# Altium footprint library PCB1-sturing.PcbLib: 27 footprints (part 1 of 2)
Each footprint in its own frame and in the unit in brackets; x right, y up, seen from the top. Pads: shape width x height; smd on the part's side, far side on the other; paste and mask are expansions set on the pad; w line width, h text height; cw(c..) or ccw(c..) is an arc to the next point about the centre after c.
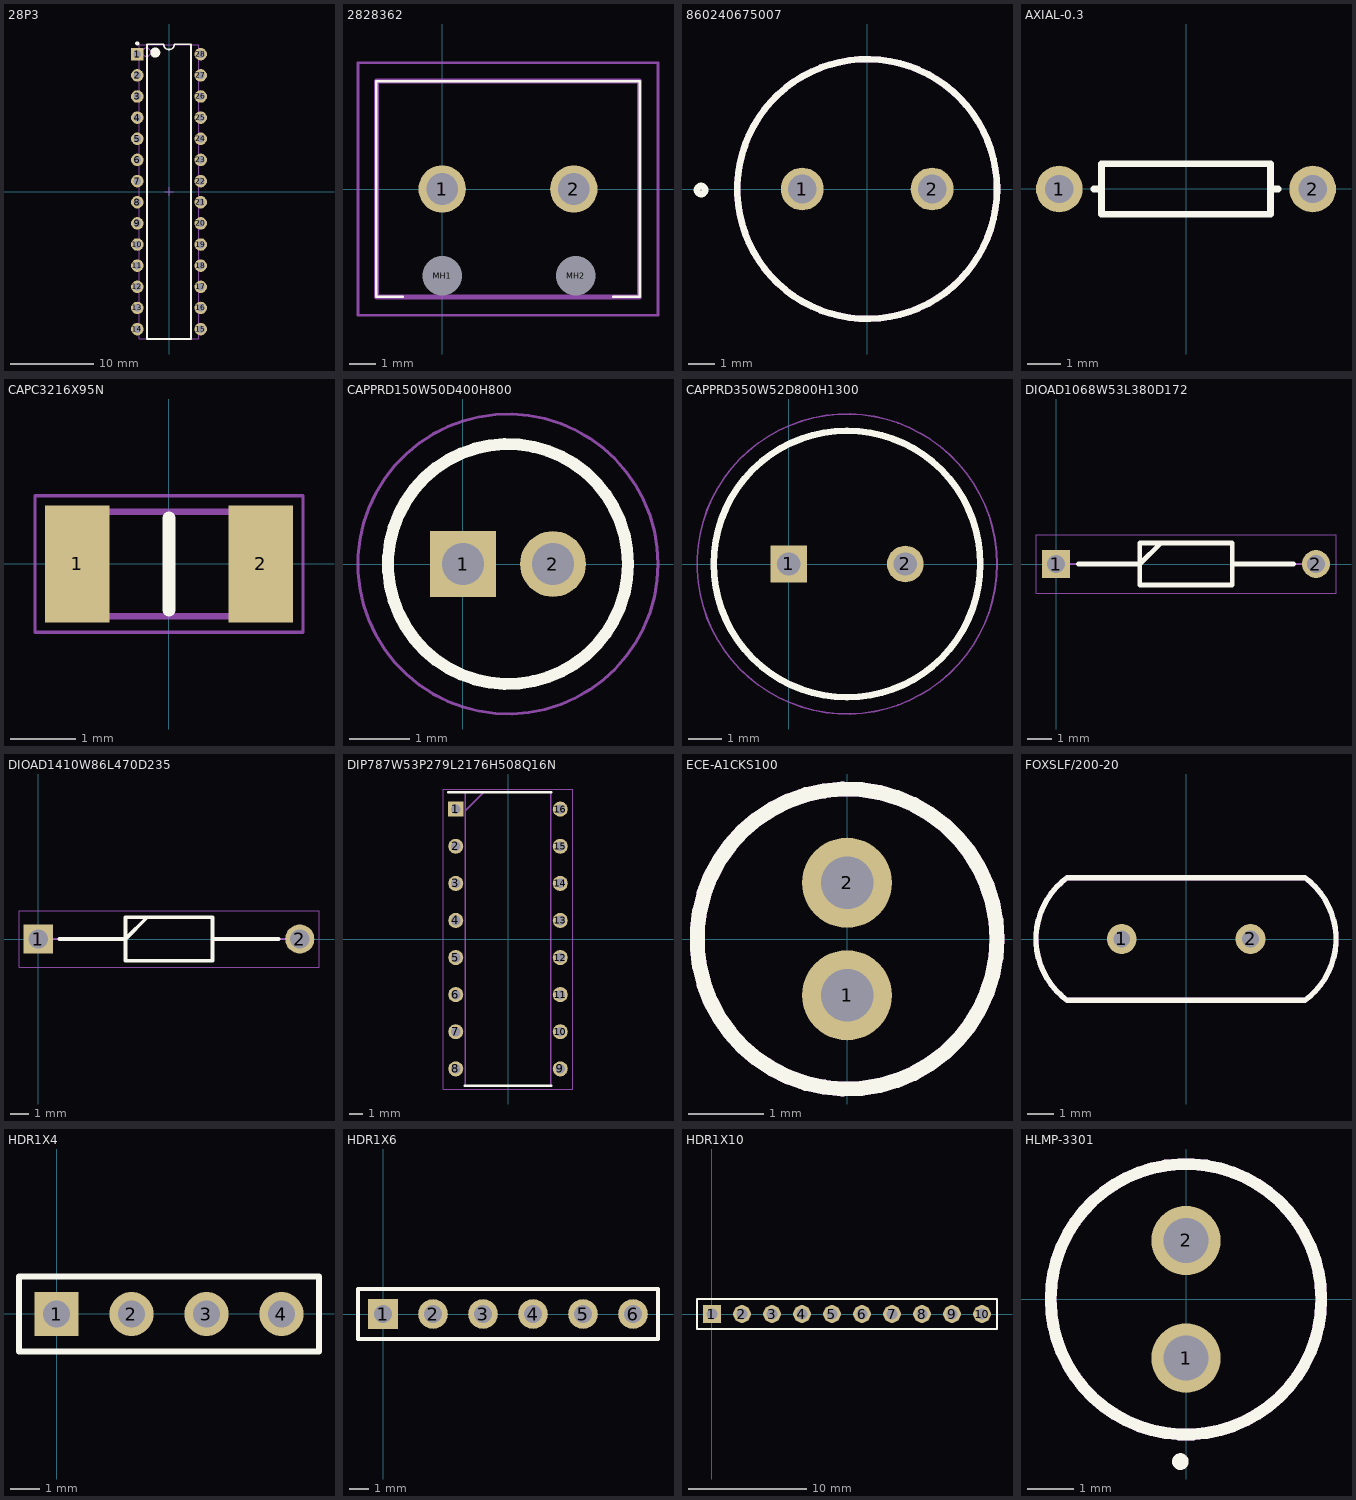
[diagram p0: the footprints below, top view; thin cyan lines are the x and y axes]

## 28P3 [mm] "28-Pin Plastic Dual In-Line Package (PDIP)"
height 4.58
pads (28):
  rect 1.5x1.5 hole 0.9: 1(-3.81,16.51)
  round 1.5 hole 0.9: 2(-3.81,13.97) 3(-3.81,11.43) 4(-3.81,8.89) 5(-3.81,6.35) 6(-3.81,3.81) 7(-3.81,1.27) 8(-3.81,-1.27) 9(-3.81,-3.81) 10(-3.81,-6.35) 11(-3.81,-8.89) 12(-3.81,-11.43) 13(-3.81,-13.97) 14(-3.81,-16.51) 15(3.81,-16.51) 16(3.81,-13.97) 17(3.81,-11.43) 18(3.81,-8.89) 19(3.81,-6.35) 20(3.81,-3.81) 21(3.81,-1.27) 22(3.81,1.27) 23(3.81,3.81) 24(3.81,6.35) 25(3.81,8.89) 26(3.81,11.43) 27(3.81,13.97) 28(3.81,16.51)
Top Overlay:
  circle w0.25: c-3.81,17.81 r0.125
  circle w0.6: c-1.65,16.7 r0.3
  lines w0.2: -2.65,-17.7 -2.65,17.7 -0.635,17.7 ccw(c0,17.7) 0.635,17.7 2.65,17.7 2.65,-17.7 -2.65,-17.7
Mechanical 13:
  circle w0.1: c-2.7,16.75 r0.5
  lines w0.1: -3.6,-17.65 -3.6,17.65 3.6,17.65 3.6,-17.65 -3.6,-17.65
Mechanical 15:
  lines w0.1: -0.5,0 0.5,0 ; 0,-0.5 0,0.5
3D body: height 4.58, standoff 0, extent -3.6,-17.65 3.6,17.65

## 2828362 [mm]
pads (4):
  round 1.8 hole 1.2: 1(0,0) 2(5,0)
  round 0.75 hole 1.5: MH1(0,-3.3) MH2(5.08,-3.3)
Top Overlay:
  lines w0.1: -1.5,-4.1 -2.5,-4.1 -2.5,4.1 7.5,4.1 7.5,-4.1 6.5,-4.1
Mechanical 13:
  lines w0.2: -2.5,-4.1 7.5,-4.1 7.5,4.1 -2.5,4.1 -2.5,-4.1
Mechanical 15:
  lines w0.1: -3.2,-4.8 8.2,-4.8 8.2,4.8 -3.2,4.8 -3.2,-4.8
3D body "282836-2.stp": height 10.2, standoff -5, extent -2.5,-4.1 7.5,4.1

## 860240675007 [mm]
pads (2):
  round 1.65 hole 1.1: 1(-2.5,0) 2(2.5,0)
Top Overlay:
  circle w0.254: c0,0 r5
  circle w0.254: c-6.395,-0.041 r0.157
Mechanical 13:
  circle w0.254: c0,0 r5

## AXIAL-0.3 [mm] "Axial Device, Thru-Hole; 2 Leads; 0.3 in Pin Spacing"
height 1.524
pads (2):
  round 1.4 hole 0.85: 1(-3.81,0) 2(3.81,0)
Top Overlay:
  lines w0.2: -2.769,0 -2.54,0 ; 2.769,0 2.54,0 ; 2.54,0 2.54,-0.762 -2.54,-0.762 -2.54,0.762 2.54,0.762 2.54,0

## CAPC3216X95N [mm]
pads (2):
  rect 0.99x1.78 smd: 1(-1.4,0) 2(1.4,0)
Top Overlay:
  lines w0.2: 0,-0.7 0,0.7
Mechanical 13:
  lines w0.1: -1.6,-0.8 -1.6,0.8 1.6,0.8 1.6,-0.8 -1.6,-0.8
Mechanical 15:
  lines w0.05: -2.045,-1.04 -2.045,1.04 2.045,1.04 2.045,-1.04 -2.045,-1.04
3D body "CC1206JRNPO9BN220.stp": height 0.95, standoff 0, extent -1.6,-0.8 1.6,0.8

## CAPPRD150W50D400H800 [mm]
pads (2):
  rect 1.1x1.1 hole 0.7: 1(0,0)
  round 1.1 hole 0.7: 2(1.5,0)
Top Overlay:
  circle w0.2: c0.75,0 r2
Mechanical 13:
  circle w0.1: c0.75,0 r2
Mechanical 15:
  circle w0.05: c0.75,0 r2.5
3D body "EEA-FC1E100.stp": height 8, standoff -10, extent -1.5,-2.247 3,2.247

## CAPPRD350W52D800H1300 [mm]
pads (2):
  rect 1.1x1.1 hole 0.7: 1(0,0)
  round 1.1 hole 0.7: 2(3.5,0)
Top Overlay:
  circle w0.2: c1.75,0 r4
Mechanical 13:
  circle w0.1: c1.75,0 r4
Mechanical 15:
  circle w0.05: c1.75,0 r4.5
3D body "860131274001.stp": height 13, standoff -10, extent -2.5,-4.25 6,4.25

## DIOAD1068W53L380D172 [mm]
pads (2):
  rect 1.15x1.15 hole 0.75: 1(0,0)
  round 1.15 hole 0.75: 2(10.7,0)
Top Overlay:
  lines w0.2: 0.925,0 3.448,0 4.308,0.86 ; 7.252,0 9.775,0 ; 3.448,-0.86 3.448,0.86 7.252,0.86 7.252,-0.86 3.448,-0.86
Mechanical 13:
  lines w0.1: 0,0 3.448,0 4.308,0.86 ; 7.252,0 10.7,0 ; 3.448,-0.86 3.448,0.86 7.253,0.86 7.253,-0.86 3.448,-0.86
Mechanical 15:
  lines w0.05: -0.825,-1.21 -0.825,1.21 11.525,1.21 11.525,-1.21 -0.825,-1.21
3D body "1N914ATR.stp": height 1.9, standoff -1.91, extent -0.264,-0.953 10.951,0.953

## DIOAD1410W86L470D235 [mm]
pads (2):
  rect 1.575x1.575 hole 1.05: 1(0,0)
  round 1.575 hole 1.05: 2(14.1,0)
Top Overlay:
  lines w0.2: 1.138,0 4.7,0 5.875,1.175 ; 9.4,0 12.962,0 ; 4.7,-1.175 4.7,1.175 9.4,1.175 9.4,-1.175 4.7,-1.175
Mechanical 13:
  lines w0.1: 0,0 4.7,0 5.875,1.175 ; 9.4,0 14.1,0 ; 4.7,-1.175 4.7,1.175 9.4,1.175 9.4,-1.175 4.7,-1.175
Mechanical 15:
  lines w0.05: -1.038,-1.525 -1.038,1.525 15.137,1.525 15.137,-1.525 -1.038,-1.525
3D body "1N4001.stp": height 2.69, standoff -2.7, extent -0.427,-1.347 14.53,1.347

## DIP787W53P279L2176H508Q16N [mil]
pads (16):
  rect 44.61x44.61 hole 28.86: 1(-155,385)
  round 44.61 hole 28.86: 2(-155,275) 3(-155,165) 4(-155,55) 5(-155,-55) 6(-155,-165) 7(-155,-275) 8(-155,-385) 9(155,-385) 10(155,-275) 11(155,-165) 12(155,-55) 13(155,55) 14(155,165) 15(155,275) 16(155,385)
Top Overlay:
  lines w7.87: -177.32,435.04 127.48,435.04 ; -127.48,-435.04 127.48,-435.04
Mechanical 13:
  lines w3.94: -127.48,380.04 -72.52,435.04 ; -127.48,-435.04 127.48,-435.04 127.48,435.04 -127.48,435.04 -127.48,-435.04
Mechanical 15:
  lines w1.97: -192.13,-444.88 192.12,-444.88 192.12,444.88 -192.13,444.88 -192.13,-444.88
3D body "SN74141.stp": height 200, standoff -137.8, extent -160.25,-428.25 160.25,428.25

## ECE-A1CKS100 [mm]
pads (2):
  round 1.2 hole 0.7: 1(0,-0.75) 2(0,0.75)
Top Overlay:
  circle w0.2: c0,0 r2
Mechanical 13:
  circle w0.2: c0,0 r2

## FOXSLF/200-20 [mm]
pads (2):
  round 1.13 hole 0.63: 1(-2.44,0) 2(2.44,0)
Top Overlay:
  lines w0.2: -4.5,-2.325 cw(c-2.816,0) -4.5,2.325 4.5,2.325 cw(c2.797,0) 4.499,-2.326 -4.5,-2.325
Mechanical 13:
  lines w0.2: -4.503,2.323 ccw(c-2.815,0) -4.499,-2.326 ; -4.5,-2.325 4.5,-2.325 ; -4.5,2.325 4.5,2.325 ; 4.498,2.326 cw(c2.796,0) 4.502,-2.323

## HDR1X4 [mm] "Connector; Header; 4 Position"
pads (4):
  rect 1.5x1.5 hole 0.9: 1(0,0)
  round 1.5 hole 0.9: 2(2.54,0) 3(5.08,0) 4(7.62,0)
Top Overlay:
  lines w0.2: -1.27,-1.27 8.89,-1.27 8.89,1.27 -1.27,1.27 -1.27,-1.27

## HDR1X6 [mm] "Connector; Header; 6 Position"
pads (6):
  rect 1.5x1.5 hole 0.9: 1(0,0)
  round 1.5 hole 0.9: 2(2.54,0) 3(5.08,0) 4(7.62,0) 5(10.16,0) 6(12.7,0)
Top Overlay:
  lines w0.2: -1.27,-1.27 13.97,-1.27 13.97,1.27 -1.27,1.27 -1.27,-1.27

## HDR1X10 [mm] "Connector; Header; 10 Position"
pads (10):
  rect 1.5x1.5 hole 0.9: 1(0,0)
  round 1.5 hole 0.9: 2(2.54,0) 3(5.08,0) 4(7.62,0) 5(10.16,0) 6(12.7,0) 7(15.24,0) 8(17.78,0) 9(20.32,0) 10(22.86,0)
Top Overlay:
  lines w0.2: -1.27,-1.27 24.13,-1.27 24.13,1.27 0.635,1.27 -1.27,1.27 -1.27,-1.27

## HLMP-3301 [mm]
pads (2):
  round 1.5 hole 0.98: 1(0,-1.27) 2(0,1.27)
Top Overlay:
  circle w0.254: c-0.122,-3.506 r0.053
  circle w0.254: c0,0 r2.923
Mechanical 13:
  circle w0.254: c0,0 r2.923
